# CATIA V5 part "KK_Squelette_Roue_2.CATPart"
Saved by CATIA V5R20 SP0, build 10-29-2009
Part number: Squelette_roue_2
Bounding box of the stored display mesh (mm): x -680 to -280, y 1056 to 1056, z -3072 to -2400
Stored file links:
  G:\Khaled_CFAO_2011\ST2M\ST2M_GR2\aboulegue\Khaled\CAD_thinkMOTION\KK_Squelette_Roue_2.CATPart
  G:\Khaled_CFAO_2011\ST2M\ST2M_GR2\aboulegue\Khaled\CAD_thinkMOTION\KK_Train_Atterrissage.CATProduct
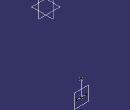
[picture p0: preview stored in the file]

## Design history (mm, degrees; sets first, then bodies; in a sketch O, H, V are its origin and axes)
Set1
  Plane1 "Plan reference": linked copy from another document
  Point1: linked copy from another document
  Point2: linked copy from another document
Set2 "Set squelette roue 2"
  Line1: type Normal, RefPoint Point1, RefSkin Plane1, Start -200, End 200
  Line2: type PtPt, FirstPoint Point1, SecondPoint Point2
  Plane2 "Plan roue 2": type 2Lines, Element1 Line1, Element2 Line2
Body1 (main body)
